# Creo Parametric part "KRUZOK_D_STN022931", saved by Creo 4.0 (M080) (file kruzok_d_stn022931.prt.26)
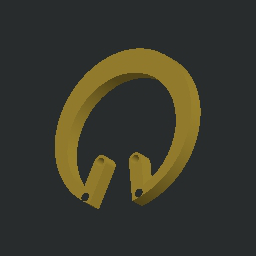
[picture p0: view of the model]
Materials in the file: OCEL_N

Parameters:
  NAZOV = "KRUZOK_D_STN022931"
  NORMA = "STN 02 2931"
  PTC_MATERIAL_NAME = "OCEL_N"

Other parameters: A, HMOTNOST, HUSTOTA, D0, D1, D5, D3, D6, D7, D8, D24, D16, D17, D12, D4

Created from: C022931.PRT

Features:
  1. datum plane "DTM1"
  2. protrusion
  3. protrusion
  4. hole
  5. hole

Other named items: COPIED_GROUP, COPIED_GROUP_1, COPIED_GROUP_2

Named dimensions: male_d2, male_d5

Layers: 1, 2, 3, 4, 5, 6, 7, 8, 9, 10, 11, 12, 13, 14, 15, 16, 17, 18, 19, 20, 21, 22, 23, 24, 25, 26, 27, 28, 29, 30, 31, 32, ROVINY

Family table entries: GENERIC, KRUZOK_D_D1_10, KRUZOK_D_STN022931, value(d_val), value(i_val), KRUZOK_D_D1_12, KRUZOK_D_STN022931, 2/), KRUZOK_D_D1_13, KRUZOK_D_STN022931, KRUZOK_D_D1_14, KRUZOK_D_STN022931, KRUZOK_D_D1_15, KRUZOK_D_STN022931, KRUZOK_D_D1_16, KRUZOK_D_STN022931, KRUZOK_D_D1_17, KRUZOK_D_STN022931, KRUZOK_D_D1_18, KRUZOK_D_STN022931, 2/3, KRUZOK_D_D1_19, KRUZOK_D_STN022931, 2/4, KRUZOK_D_D1_20, KRUZOK_D_STN022931, 2/5, KRUZOK_D_D1_21, KRUZOK_D_STN022931, 2/6, KRUZOK_D_D1_22, KRUZOK_D_STN022931, 2/7, KRUZOK_D_D1_24, KRUZOK_D_STN022931, KRUZOK_D_D1_25, KRUZOK_D_STN022931, KRUZOK_D_D1_26, KRUZOK_D_STN022931, KRUZOK_D_D1_28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

Surfaces: 6 plane, 4 cylinder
